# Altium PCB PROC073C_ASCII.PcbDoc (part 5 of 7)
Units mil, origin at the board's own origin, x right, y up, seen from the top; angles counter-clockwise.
Board outline 2165.35 x 2695.12 mil, 8 copper layers (Top Layer, L2_GND, L3_SIGNAL 1, L4_SIGNAL 2, L5_SIGNAL 3, L6_SIGNAL 4, L7_GND, Bottom Layer), stack 55.9 mil thick; 393 components, 319 nets, 1311 pads, 1643 vias.
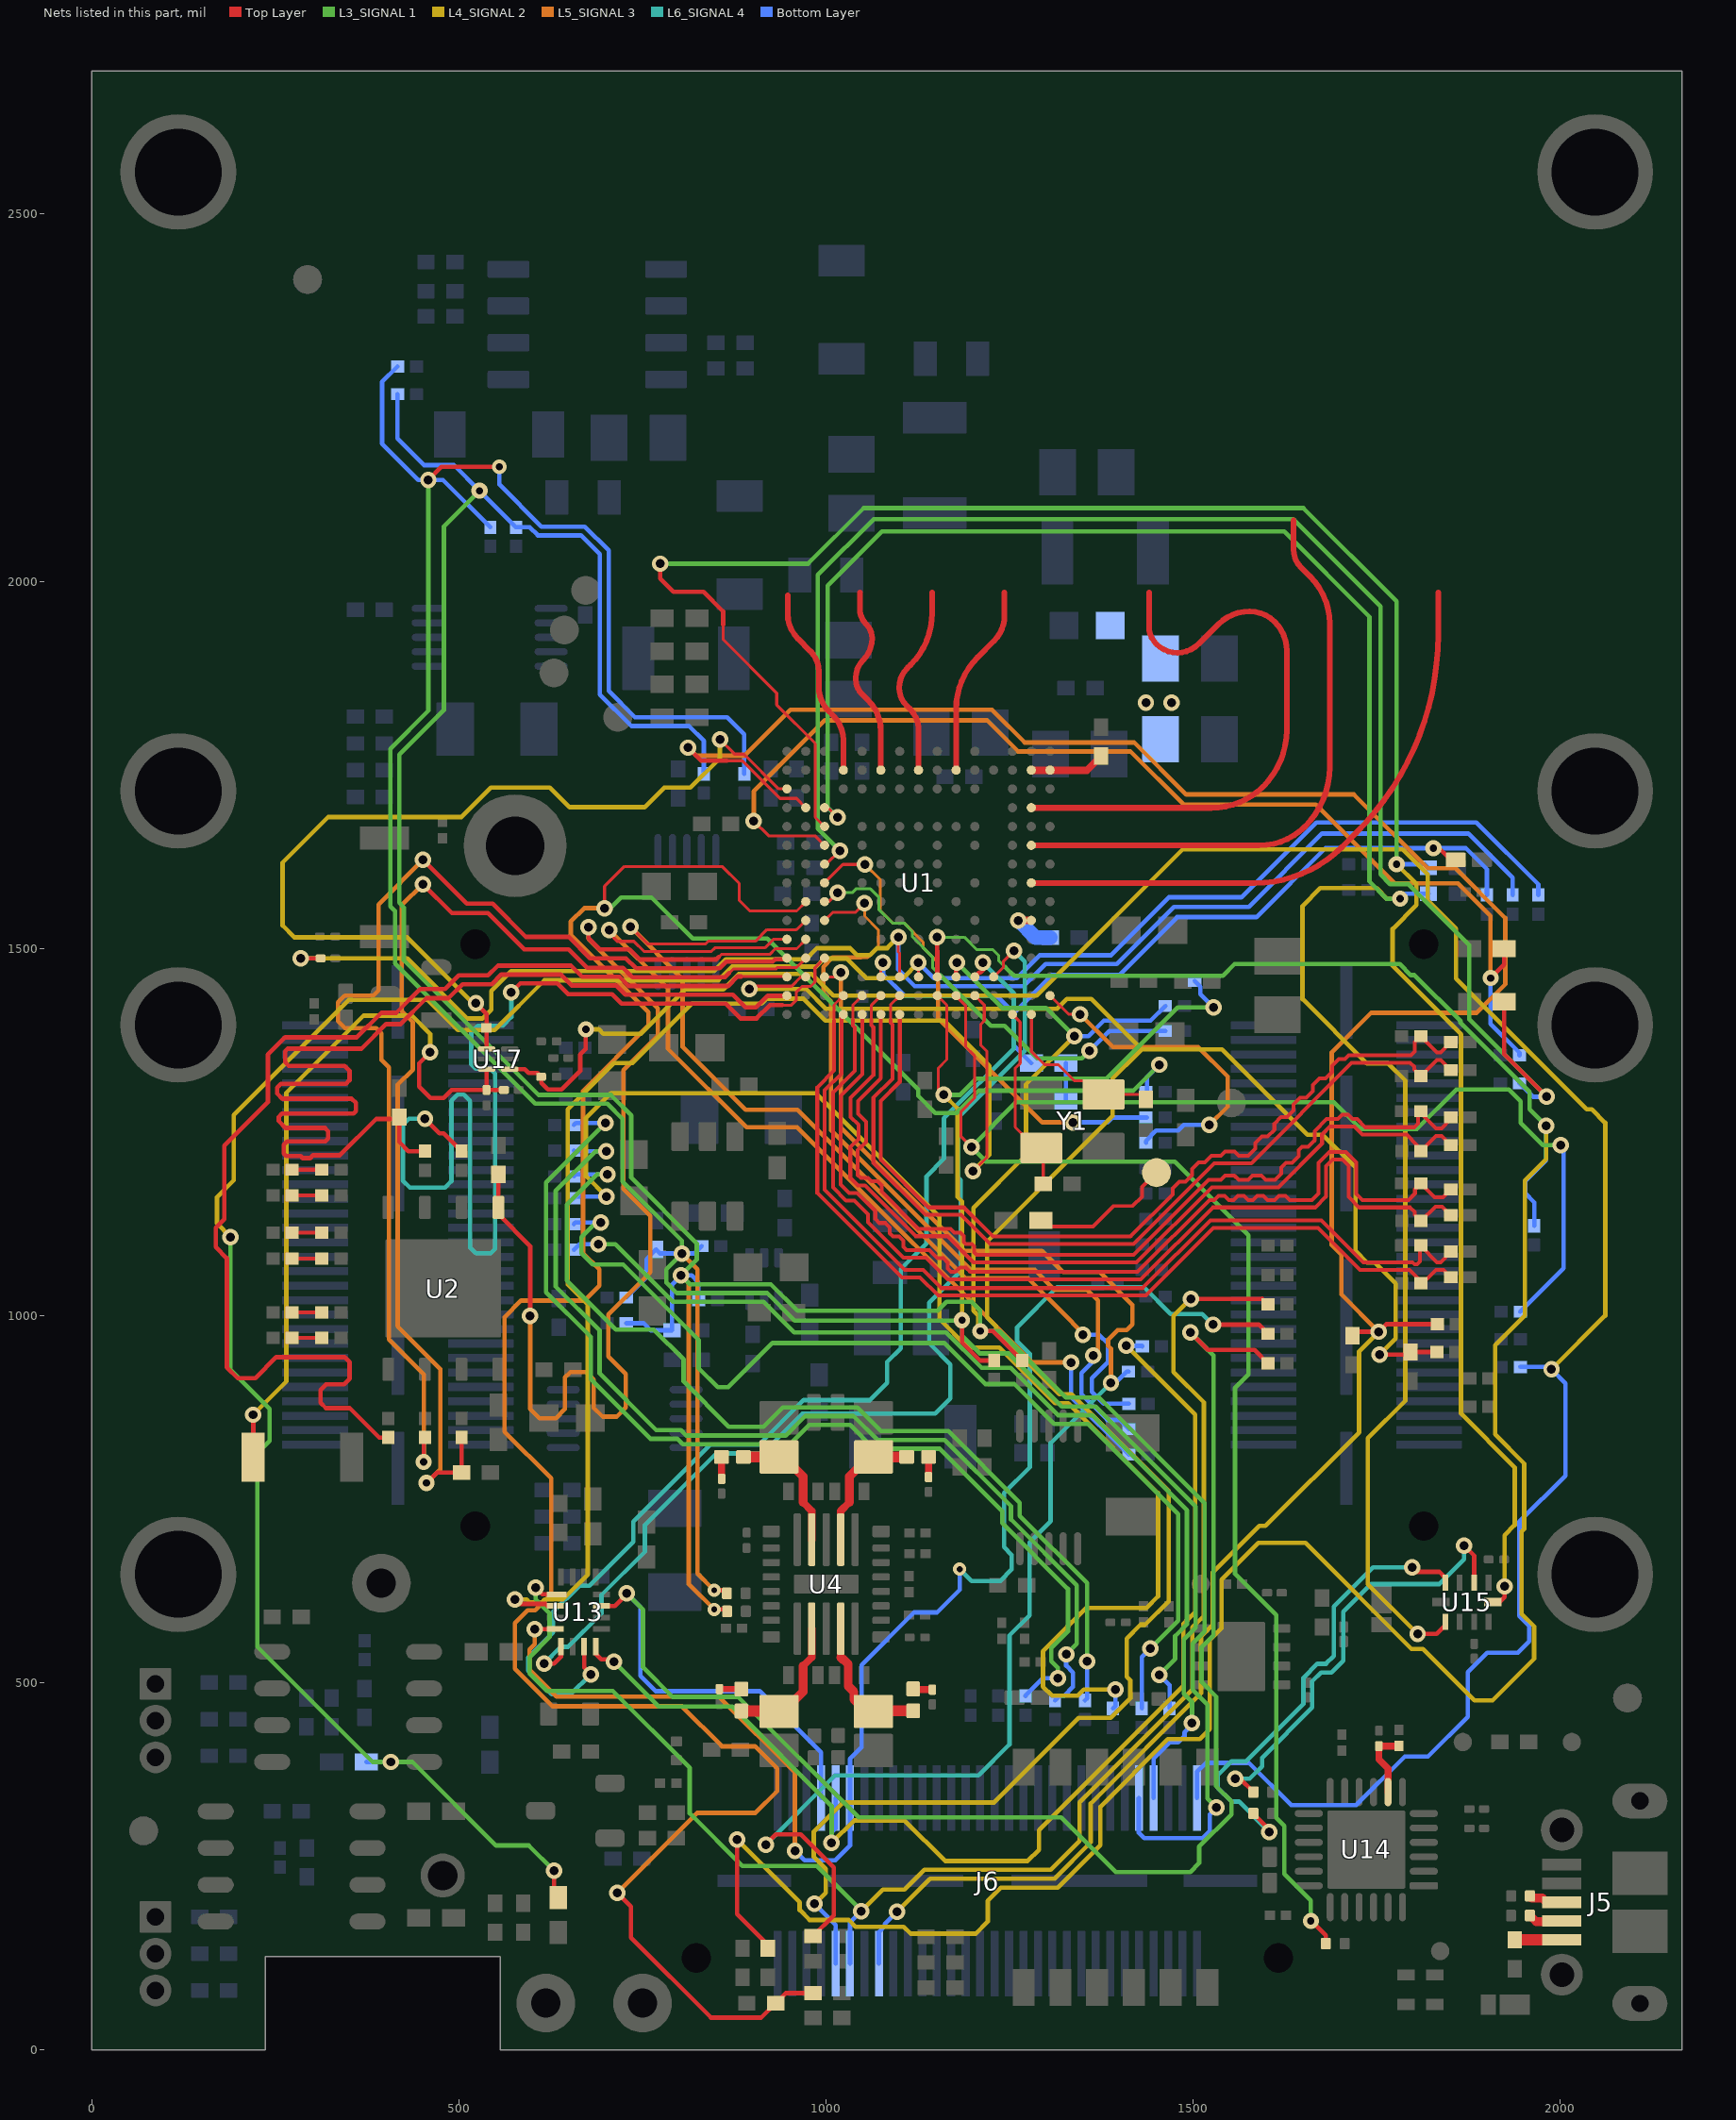
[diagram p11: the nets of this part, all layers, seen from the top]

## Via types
v1: diameter 15.74, hole 5.9, Top Layer to L2_GND, tented both sides, 894 vias
v2: diameter 22.4, hole 12.2, Top Layer to Bottom Layer, tented both sides, 510 vias
v3: diameter 18, hole 8, Top Layer to Bottom Layer, tented both sides, 74 vias
v4: diameter 15.75, hole 5.9, Top Layer to L2_GND, tented both sides, 72 vias
v5: diameter 22, hole 10, Top Layer to Bottom Layer, tented both sides, 61 vias
v6: diameter 19.68, hole 7.87, Top Layer to Bottom Layer, 16 vias
v7: diameter 15.74, hole 5.9, Top Layer to L2_GND, tented top, 14 vias
v8: diameter 20, hole 10, Top Layer to Bottom Layer, tented both sides, 1 vias
v9: diameter 15.75, hole 5.9, Top Layer to L2_GND, tented top, 1 vias

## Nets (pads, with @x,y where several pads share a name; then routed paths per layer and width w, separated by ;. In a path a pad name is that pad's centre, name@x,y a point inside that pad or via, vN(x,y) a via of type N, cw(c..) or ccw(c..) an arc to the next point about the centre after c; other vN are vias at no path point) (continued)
RADAR_DP10: R126.1 R163.1 | length 1440
  L3_SIGNAL 1 w6: v2(699.88,1262.31) 619.04,1181.47 619.04,1031.78 679.65,971.18 679.65,913.63 760.82,832.46 797.34,832.46 804.96,824.84 950.77,824.84 977.15,851.21 1032.87,851.21 1065.23,818.85 1155.14,818.85 1239.93,734.06 1239.93,717.61 1329.48,628.05 1329.48,569.87 1306.87,547.26 1306.87,529.59 1315.67,520.79 v2(1315.67,506.35)
  Bottom Layer w6: R126.1@656.74,1259.77 659.27,1262.31 v2(699.88,1262.31) ; R163.1@1271.67,482.2 1271.67,482.61 1295.41,506.35 v2(1315.67,506.35)
RADAR_DP11: R127.1 R164.1 | length 1390.6
  L3_SIGNAL 1 w6: v2(700.77,1224.08) 686.3,1224.08 631.92,1169.7 631.92,1039.89 691.77,980.04 691.77,921.47 768.79,844.46 802.31,844.46 809.93,836.84 944.98,836.84 971.35,863.21 1037.85,863.21 1070.2,830.85 1161.65,830.85 1251.93,740.57 1251.93,722.58 1341.48,633.03 1341.48,553.3 v2(1327.07,538.89)
  Bottom Layer w6: R127.1@656.74,1224.77 657.43,1224.08 v2(700.77,1224.08) ; R164.1@1311.95,476.21 1318.5,482.76 1324.58,482.76 1336.41,494.6 1336.41,514.17 1327.07,523.51 v2(1327.07,538.89)
RADAR_DP12: R128.1 R166.1 | length 1313
  L3_SIGNAL 1 w6: v2(702.64,1192.32) 687.92,1192.32 647.04,1151.44 647.04,1047.9 713.7,981.24 765.35,981.24 806.14,940.45 806.14,910.34 867.64,848.84 914.85,848.84 941.22,875.21 1042.82,875.21 1075.17,842.85 1166.62,842.85 1263.93,745.54 1263.93,727.55 1355.47,636 v2(1355.47,529.24)
  Bottom Layer w6: R128.1@656.74,1189.77 659.28,1192.32 v2(702.64,1192.32) ; R166.1@1352.68,476.21 1355.47,479 v2(1355.47,529.24)
RADAR_DP13: R129.1 R167.1 | length 1774.4
  L4_SIGNAL 2 w6: v2(701,1162.39) 673.21,1190.18 673.21,1269.31 706.86,1302.96 986.35,1302.96 1154.49,1134.82 1154.49,995.55 1193.3,956.74 1236.32,956.74 1312.09,880.97 1329.87,880.97 1452.29,758.55 1452.29,617.94 1436.42,602.07 1354.52,602.07 1295.47,543.01 1295.47,495.14 1307.84,482.76 1342.8,482.76 1351.01,490.97 v2(1394.13,490.97)
  Bottom Layer w6: R129.1@656.74,1159.77 659.35,1162.39 v2(701,1162.39) ; R167.1@1390.77,465.36 1394.13,468.72 v2(1394.13,490.97)
RADAR_DP14: R130.1 R168.1 | length 1411.3
  L3_SIGNAL 1 w6: v2(693.46,1126.8) 686.72,1126.8 666.87,1106.95 666.87,1085.41 682.46,1069.82 723.86,1069.82 826.64,967.04 826.64,928.67 852.61,902.69 867.01,902.69 927.16,962.84 1161.12,962.84 1216.94,907.02 1256.38,907.02 1310.83,852.56 1357.04,852.56 1479.54,730.07 1479.54,585.01 v2(1441.67,547.13)
  Bottom Layer w6: R130.1@656.74,1124.77 658.77,1126.8 v2(693.46,1126.8) ; R168.1@1429.92,465.36 1429.92,535.38 v2(1441.67,547.13)
RADAR_DP15: R132.1 R170.1 | length 1279.2
  L3_SIGNAL 1 w6: v2(690.39,1097.28) 713.37,1097.28 791.76,1018.88 915,1018.88 956.59,977.29 1163.64,977.29 1212.04,928.89 1251.48,928.89 1315.8,864.56 1362.01,864.56 1491.54,735.04 1491.54,580.04 1475.43,563.92 1475.43,532.9 v2(1453.69,511.16)
  Bottom Layer w6: R132.1@656.74,1089.77 664.24,1097.28 v2(690.39,1097.28) ; v2(1453.69,511.16) 1467.83,497.01 R170.1@1467.83,465.36
RADAR_GPIO_0: R3.2 R65.1 R216.2 U1.H13 | length 3456.1
  Top Layer w4: v2(1125.87,1480.63) 1125.97,1480.53 U1.H13@1125.98,1461.43
  Top Layer w6: v2(629.66,244.32) 629.66,213.6 R216.2@635.54,207.72
  L3_SIGNAL 1 w6: v2(189.22,1107.14) 189.22,926.5 242.35,873.38 242.35,829.52 225.74,812.92 225.74,549.14 382.47,392.41 v2(407.49,392.41) 436.79,392.41 550.58,278.62 595.36,278.62 v2(629.66,244.32)
  L4_SIGNAL 2 w6: v2(189.22,1107.14) 170.88,1125.48 170.88,1161.52 193.76,1184.4 193.76,1273.34 350.5,1430.09 457.6,1430.09 498.52,1389.16 549.01,1389.16 616.58,1456.73 853.54,1456.73 872.19,1475.39 986.79,1475.39 997.78,1486.39 1027.98,1486.39 1054.73,1459.63 1104.88,1459.63 v2(1125.87,1480.63)
  Bottom Layer w6: R3.2@374.13,392.41 v2(407.49,392.41) ; v2(1125.87,1480.63) 1146.7,1459.8 1260.03,1459.8 1290.94,1490.71 1387.94,1490.71 1467,1569.77 1565.72,1569.77 1667.66,1671.71 1885.71,1671.71 1970,1587.42 R65.1@1970,1572.76
RADAR_GPIO_1: R66.2 R214.2 U1.J13 | length 2022.3
  Top Layer w4: v2(1098.42,1515.43) 1098.42,1495.23 1100.38,1493.27 U1.J13@1100.39,1461.43
  Top Layer w6: v2(284.89,1486.65) R214.2@311.88,1486.65
  L4_SIGNAL 2 w6: v2(284.89,1486.65) 429.79,1486.65 511.81,1404.63 531.99,1404.63 544.12,1416.76 544.12,1442.11 571.24,1469.23 847.52,1469.23 863.68,1485.39 972.74,1485.39 987.85,1500.51 1032.72,1500.51 1042.13,1491.09 1060.05,1491.09 1069.46,1500.51 1083.5,1500.51 v2(1098.42,1515.43)
  Bottom Layer w6: v2(1098.42,1515.43) 1098.42,1471.34 1120.84,1448.93 1269.16,1448.93 1298.94,1478.71 1395.94,1478.71 1474,1556.77 1575.75,1556.77 1675.59,1656.61 1874.64,1656.61 1935,1596.25 R66.2@1935,1572.76
RADAR_GPIO_2: D7.1 R67.2 R185.2 U1.K13 | length 1149.4
  Top Layer w4: U1.K13@1074.8,1461.43 1074.79,1477.71 v2(1077.67,1480.59)
  Top Layer w6: v5(1827.1,1636.61) 1827.1,1637.93 1830.3,1641.13 1850.63,1620.81 D7.1@1857.59,1620.81
  Bottom Layer w6: v2(1077.67,1480.59) 1077.67,1465.1 1106.92,1435.86 1232.34,1435.86 1251.05,1417.15 ; R185.2@1279.5,1344.13 1256,1367.63 1256,1412.2 ; R67.2@1900,1572.76 1900,1608.03 1871.42,1636.61 v5(1827.1,1636.61) 1679.81,1636.61 1585.97,1542.77 1478,1542.77 1399,1463.77 1307.57,1463.77 1260.95,1417.15 ; 1251.05,1417.15 1256,1412.2 ; 1251.05,1417.15 1260.95,1417.15 ; 1256,1412.2 1260.95,1417.15
RADAR_HOSTINTR1: J6.10 R10.2 R152.2 U1.P13 | length 3227.2
  Top Layer w4: v2(895.59,1444.77) 899.55,1448.72 953.35,1448.72 965.85,1461.22 U1.P13@972.64,1461.22
  Top Layer w6: v2(1754.07,947.16) 1792.52,947.16 R152.2@1795.94,950.58 R10.2@1831.68,950.58
  L4_SIGNAL 2 w6: v2(895.59,1444.77) 973.05,1444.77 999.88,1417.94 1314.72,1417.94 1328.02,1431.24 1361.41,1431.24 1424.28,1368.37 ; v2(984.35,199.12) 999.65,214.42 999.65,246.71 983.46,262.9 983.46,297.43 1023.24,337.21 1228.81,337.21 1343.92,452.32 1387.89,452.32 1414.33,478.76 1414.33,503.62 1409.47,508.48 1409.47,560.46 1428.33,579.33 1434.57,579.33 1466.56,611.31 1466.56,761.25 1334.52,893.29 1317.77,893.29 1231.45,979.61 1231.45,985.86 1219.49,997.83 1219.49,1100.93 1390.36,1271.81 1390.36,1323.23 1424.28,1357.15 ; v2(1754.07,947.16) 1775.89,968.97 1775.89,1044.14 1747.57,1072.45 1736.75,1072.45 1721.01,1088.19 1721.01,1201.86 1676.32,1246.55 1655.67,1246.55 1539.46,1362.76 1429.89,1362.76 ; 1424.28,1357.15 1429.89,1362.76 ; 1424.28,1357.15 1424.28,1368.37 ; 1424.28,1368.37 1429.89,1362.76
  Bottom Layer w6: v2(984.35,199.12) 1013.05,170.43 J6.10@1013.05,117.69
RADAR_INTn: R184.1 R185.1 | length 51.8
  Bottom Layer w6: R184.1@1326.74,1292.36 R185.1@1326.74,1344.13
RADAR_LVDS_0M: R41.2 R230.2 U1.J15 | length 1201.9
  Top Layer w5.2: U1.J15@1100.59,1410.04 1100.59,1318.34 1074.79,1292.54 1074.79,1212.36 1139.67,1147.47 1187.93,1147.47 1227.63,1107.77 1414.67,1107.77 1472.09,1165.19 1472.09,1173.45 1481.04,1182.4 1489.29,1182.4 1498.36,1191.46 1498.36,1199.72 1507.31,1208.67 1515.57,1208.67 1524.63,1217.73 1537.76,1217.73 1543.6,1223.57 1556.26,1223.57 1562.1,1217.73 1574.91,1217.73 1584.35,1227.16 1584.35,1235.42 1593.3,1244.37 1601.56,1244.37 1610.62,1253.44 1610.62,1261.69 1619.57,1270.64 1627.83,1270.64 1636.89,1279.71 1636.89,1287.96 1645.84,1296.92 1654.1,1296.92 1663.16,1305.98 1663.16,1314.24 1672.11,1323.19 1680.37,1323.19 1689.43,1332.25 1689.43,1340.51 1698.38,1349.46 1706.64,1349.46 1711.65,1354.46 1796.37,1354.46 1801.8,1359.89 1801.8,1372.67 R230.2@1809.84,1380.71 1810.22,1380.32 1832.02,1358.52 1836.91,1358.52 R41.2@1850.8,1372.41
RADAR_LVDS_0P: R39.2 R229.2 U1.J14 | length 1203.4
  Top Layer w4: 1087.88,1402.84 1087.88,1423.35 U1.J14@1100.39,1435.84
  Top Layer w5.2: 1087.88,1402.84 1087.88,1398.83 1090.39,1396.32 1090.39,1322.57 1064.59,1296.77 1064.59,1208.13 1135.45,1137.28 1183.71,1137.28 1223.41,1097.57 1418.89,1097.57 1528.85,1207.53 1579.14,1207.53 1715.87,1344.26 1795.48,1344.26 1800.81,1338.93 1800.81,1335.25 R229.2@1809.84,1326.22 R229.2@1810.22,1326.6 ; R229.2@1810.26,1326.57 R229.2@1810.22,1326.6 ; R39.2@1850.8,1334.43 1836.91,1348.32 1831.94,1348.32 R229.2@1810.22,1326.6
RADAR_LVDS_1M: R35.2 R228.2 U1.K15 | length 1255.8
  Top Layer w5.2: U1.K15@1074.8,1410.25 1074.79,1323.47 1043.72,1292.4 1043.72,1274.8 1054.39,1264.13 1054.39,1236.34 1043.35,1225.3 1043.35,1191.73 1047.68,1187.41 1057.31,1187.41 1061.69,1183.02 1069.95,1183.02 1075.8,1177.17 1075.8,1168.92 1126.21,1118.5 1169.48,1118.5 1174.86,1113.12 1183.12,1113.12 1187.64,1108.6 1187.64,1100.34 1190.37,1097.61 1198.62,1097.61 1201.69,1094.55 1201.69,1086.29 1205.01,1082.97 1418.72,1082.97 1520.99,1185.24 1537.51,1185.24 1543.35,1191.08 1556.01,1191.08 1561.84,1185.24 1574.66,1185.24 1580.5,1191.08 1593.16,1191.08 1599,1185.24 1611.81,1185.24 1619.89,1193.33 1619.89,1201.58 1626.27,1207.96 1634.52,1207.96 1643.59,1217.02 1643.59,1225.28 1648.44,1230.13 1656.7,1230.13 1665.28,1238.71 1665.28,1251.05 1681.86,1267.63 1697.24,1267.63 1703.07,1273.47 1711.34,1273.47 1717.18,1267.63 1723.38,1267.63 1734.37,1256.65 1801.32,1256.65 1805.97,1261.31 1805.97,1274.65 R228.2@1809.84,1278.52 1809.84,1275.68 1830.33,1255.19 1838.34,1255.19 1850.8,1267.65 R35.2@1850.8,1270.22
RADAR_LVDS_1P: R33.2 R227.2 U1.K14 | length 1254.7
  Top Layer w4: 1061.87,1402.84 1061.87,1422.93 U1.K14@1074.8,1435.84
  Top Layer w5.2: 1061.87,1402.84 1061.87,1395.54 1064.59,1392.82 1064.59,1327.69 1033.52,1296.62 1033.52,1270.57 1044.19,1259.9 1044.19,1240.57 1033.52,1229.9 1033.15,1229.53 1033.15,1187.51 1043.45,1177.21 1053.08,1177.21 1121.98,1108.3 1165.25,1108.3 1200.79,1072.77 1422.94,1072.77 1525.22,1175.04 1616.04,1175.04 1675.48,1234.48 1675.48,1246.82 1686.09,1257.43 1719.16,1257.43 1730.14,1246.45 1790.86,1246.45 1805.16,1232.15 1805.16,1229.48 R227.2@1810.26,1224.38 1830.88,1244.99 1838.04,1244.99 R33.2@1850.8,1232.24
RADAR_LVDS_2M: R137.2 R224.2 | length 40.6
  Top Layer w5.2: R137.2@272.99,969.77 R224.2@313.6,969.77
RADAR_LVDS_2P: R136.2 R223.2 | length 40.6
  Top Layer w5.2: R136.2@272.99,1004.77 R223.2@313.6,1004.77
RADAR_LVDS_3M: R135.2 R222.2 | length 40.6
  Top Layer w5.2: R135.2@272.99,1078.02 R222.2@313.6,1078.02
RADAR_LVDS_3P: R134.2 R221.2 | length 40.6
  Top Layer w5.2: R134.2@272.99,1113.02 R221.2@313.6,1113.02
RADAR_LVDS_CLKM: R32.2 R226.2 U1.L15 | length 1338
  Top Layer w5.2: U1.L15@1049.41,1410.04 1049.41,1392.62 1049.4,1329 1019.78,1299.39 1019.78,1178.79 1031.58,1166.99 1042.55,1166.99 1067.21,1142.34 1067.21,1131.66 1072.61,1126.27 1080.86,1126.27 1086.71,1120.42 1086.71,1112.16 1091.1,1107.78 1099.35,1107.78 1105.2,1101.93 1105.2,1093.67 1109.59,1089.29 1140.54,1089.29 1151.67,1078.16 1159.93,1078.16 1165.77,1072.31 1165.77,1064.06 1170.16,1059.67 1176.36,1059.67 1182.2,1065.51 1190.47,1065.51 1196.31,1059.67 1424.27,1059.67 1522.26,1157.66 1528.8,1157.66 1534.64,1163.5 1542.91,1163.5 1548.75,1157.66 1554.95,1157.66 1560.79,1163.5 1569.06,1163.5 1574.89,1157.66 1581.1,1157.66 1586.94,1163.5 1595.61,1163.5 1601.45,1157.66 1610.84,1157.66 1616.68,1163.5 1625.64,1163.5 1631.48,1157.66 1661.78,1157.66 1670.6,1166.48 1670.6,1208.13 1685.54,1223.07 1707.71,1223.07 1722.02,1208.76 1722.02,1166.07 1730.42,1157.66 1793.15,1157.66 1802.02,1166.53 1802.02,1172.36 R226.2@1809.84,1180.18 1828.71,1161.32 1840.22,1161.32 R32.2@1850.8,1171.89
RADAR_LVDS_CLKP: R30.2 R225.2 U1.L14 | length 1346.1
  Top Layer w4: 1036.49,1402.62 1036.49,1422.71 U1.L14@1049.41,1435.63
  Top Layer w5.2: 1036.49,1402.62 1036.49,1395.32 1039.2,1392.61 1039.2,1333.23 1009.58,1303.61 1009.58,1174.56 1027.35,1156.79 1038.33,1156.79 1057.01,1138.11 1057.01,1127.44 1105.36,1079.09 1136.32,1079.09 1165.93,1049.47 1428.49,1049.47 1526.49,1147.46 1666,1147.46 1680.8,1162.26 1680.8,1203.91 1689.76,1212.87 1703.48,1212.87 1711.82,1204.54 1711.82,1161.84 1726.2,1147.46 1795.54,1147.46 1801.6,1141.41 1801.6,1137.69 R225.2@1810.26,1129.03 1829.86,1148.63 1839.06,1148.63 R30.2@1850.8,1136.89
RADAR_LVDS_FRCLKM: R24.2 R220.2 U1.M15 | length 1258.7
  Top Layer w5.2: U1.M15@1023.82,1410.04 1021.27,1407.5 1021.27,1329.73 998.4,1306.85 998.4,1171.32 1107.5,1062.22 1132.37,1062.22 1156.93,1037.66 1431.11,1037.66 1523.33,1129.89 1674.32,1129.89 1731.42,1072.79 1798.58,1072.79 1801.47,1069.89 1804.71,1069.89 1808.54,1073.73 1808.54,1093.74 R220.2@1809.84,1095.03 ; R220.2@1809.84,1095.72 R220.2@1809.84,1095.03 ; R24.2@1850.8,1087.42 1850.8,1086.58 1836.91,1072.7 1832.17,1072.7 R220.2@1809.84,1095.03
RADAR_LVDS_FRCLKP: R22.2 R219.2 U1.M14 | length 1285.9
  Top Layer w4: 1011.07,1401.47 1011.07,1423.3 U1.M14@1023.62,1435.84
  Top Layer w5.2: 1011.07,1401.47 1011.07,1333.95 988.2,1311.08 988.2,1167.1 1103.27,1052.02 1128.15,1052.02 1152.7,1027.47 1435.34,1027.47 1527.56,1119.69 1670.09,1119.69 1727.19,1062.59 1794.36,1062.59 1810.26,1046.68 R219.2@1810.26,1044.56 1812.79,1044.56 1830.59,1062.36 1840.86,1062.36 R22.2@1850.8,1052.42
RADAR_LVDS_VALIDM: R133.2 R218.2 | length 40.6
  Top Layer w5.2: R133.2@272.99,1163.84 R218.2@313.6,1163.84
RADAR_LVDS_VALIDP: R131.2 R217.2 | length 40.6
  Top Layer w5.2: R131.2@272.99,1198.84 R217.2@313.6,1198.84
RADAR_MCUCLKOUT: R62.2 U1.N8 | length 671
  Top Layer w4: U1.N8@998.03,1589.39 1007.57,1598.94 1007.57,1599 1023.06,1614.49 v2(1053.07,1614.49)
  L5_SIGNAL 3 w4: v2(1053.07,1614.49) 1073.87,1593.69 1073.87,1551.33 1090.58,1534.63 1106.38,1534.63 1132.27,1508.73 1132.27,1501.38 1152.74,1480.91 1152.74,1453.84
  L5_SIGNAL 3 w6: 1152.74,1453.84 1152.74,1405.22 1294.64,1263.32 v2(1336.33,1263.32)
  Bottom Layer w6: v2(1336.33,1263.32) 1383.35,1263.32 1389.8,1269.77 R62.2@1437.01,1269.77
RADAR_MISO1: U1.E14 U13.2 | length 1904.6
  Top Layer w4: v2(1200,1196.67) 1219.29,1215.96 1219.29,1359.77 1210.95,1368.11 1210.95,1397.1 1215.5,1401.65 1215.5,1423.09 U1.E14@1202.95,1435.63
  Top Layer w6: v2(576.47,613.51) 582.4,607.58 617.96,607.58 620.72,604.82 U13.2@631.29,604.82
  L4_SIGNAL 2 w6: v2(576.47,613.51) 592.29,613.51 596.31,609.49 613.05,609.49 617.07,613.51 641.66,613.51 675.76,647.61 675.76,1015.28 648.54,1042.5 648.54,1280.98 711.53,1343.97 736.64,1343.97 817.51,1424.84 912.52,1424.84 919.49,1431.82 969.06,1431.82 999.06,1401.81 1161.01,1401.81 1222.47,1340.35 1222.47,1219.14 v2(1200,1196.67)
RADAR_MOSI1: U1.D13 U13.5 | length 1511.4
  Top Layer w4: U1.D13@1228.54,1461.22 1241.43,1474.11 1241.43,1482.29 v2(1256.07,1496.94)
  Top Layer w6: v2(616.38,526.51) 629.95,526.51 639.17,535.72 U13.5@639.17,549.7
  L6_SIGNAL 4 w6: v2(616.38,526.51) 639.05,549.19 649.15,549.19 694.33,594.37 694.33,619.78 753.44,678.89 753.44,715 850.96,812.52 913.82,812.52 968,866.7 1148.95,866.7 1169.49,887.23 1169.49,933.77 1140.49,962.77 1140.49,1017.69 1183.66,1060.86 1183.66,1184.45 1179.75,1188.36 1179.75,1269.45 1270.88,1360.58 1270.88,1482.14 v2(1256.07,1496.94)
RADAR_MSS_LOGGER: R31.2 R96.2 U1.F14 | length 2847.5
  Top Layer w4: U1.F14@1177.16,1435.84 1177.15,1435.16 1189.87,1422.44 ; 1190.28,1422.03 1190.28,1366.12 1202.29,1354.12 1202.29,1296.09 1183.59,1277.39 1183.59,1244.26 v2(1197.95,1229.9)
  Top Layer w6: v5(1660.15,176.07) 1660.79,176.07 1680.69,156.17 R96.2@1680.69,145.26
  L3_SIGNAL 1 w6: v5(1660.15,176.07) 1660.15,203.84 1623.96,240.03 1623.96,305.54 1613.03,316.47 1613.03,592.63 1556.86,648.8 1556.86,901.54 1575.37,920.06 1575.37,1109.78 1475.19,1209.97 1376.46,1209.97 1217.88,1209.96 v2(1197.95,1229.9) 1258.78,1290.73 1691.76,1290.73 1728.06,1254.43 1804.48,1254.43 1858.29,1308.25 1929.75,1308.25 1946.07,1291.93 1946.07,1262.46 1976.13,1232.4 v2(2000.74,1232.4)
  Bottom Layer w6: R31.2@1945.35,1005.51 2004.53,1064.69 2004.53,1228.61 v2(2000.74,1232.4)
RADAR_NERR_OUT: R59.2 R169.1 U1.N6 | length 1558.3
  Top Layer w4: v2(901.68,1673.63) 921.88,1653.43 985.16,1653.43 U1.N6@998.23,1640.36
  Top Layer w6: v5(1905,1459.77) 1923.62,1478.39 R169.1@1923.62,1499.77
  L5_SIGNAL 3 w6: v2(901.68,1673.63) 901.68,1714.22 998.24,1810.79 1219.09,1810.79 1261.57,1768.31 1414.77,1768.31 1487.2,1695.88 1667.01,1695.88 1774.14,1588.74 1860.68,1588.74 1905,1544.42 v5(1905,1459.77)
  Bottom Layer w6: v5(1905,1459.77) 1905,1397.31 1944.29,1358.02 R59.2@1944.29,1354.7
RADAR_NERRIN: R58.2 R150.1 U1.N7 | length 2237.2
  Top Layer w4: U1.N7@998.03,1614.98 1000.46,1614.98 v2(1018.77,1633.29)
  Top Layer w6: R150.1@1923.62,1427.68 1923.62,1355.98 v2(1981.41,1298.19)
  L3_SIGNAL 1 w6: v2(1018.77,1633.29) 989,1663.06 989,2008.77 1065,2084.77 1636.12,2084.77 1755,1965.89 1755,1600.77 1768.01,1587.75 1793.19,1587.75 1876.06,1504.88 1876.06,1403.54 v2(1981.41,1298.19)
  Bottom Layer w6: R58.2@1944.29,1316.46 1962.57,1298.18 ; 1962.58,1298.19 v2(1981.41,1298.19)
RADAR_NRST: R171.1 U1.R3 U17.4 | length 1282.2
  Top Layer w4: v2(855.59,1784.77) 875.59,1764.77 888.22,1764.77 935.65,1717.34 U1.R3@946.84,1717.34
  Top Layer w6: v2(523.42,1425.33) 537.82,1410.93 R171.1@537.82,1391.99 U17.4@537.82,1363.26
  L4_SIGNAL 2 w6: v2(523.42,1425.33) 519.52,1425.33 429.54,1515.31 276.09,1515.31 260.09,1531.31 260.09,1616.75 322.38,1679.05 503.63,1679.05 543.89,1719.31 623.83,1719.31 650.75,1692.39 753.08,1692.39 779.77,1719.08 815.37,1719.08 855.59,1759.3 v2(855.59,1784.77)
RADAR_NRST_1: J6.59 R42.1 R123.2 U17.1 | length 3381.3
  Top Layer w6: U17.1@569.32,1335.7 590,1335.7 595.18,1330.51 607.03,1330.51 R123.2@612.21,1325.33 612.21,1317.3 621.65,1307.86 639.85,1307.86 665.35,1333.36 665.35,1355.41 672.99,1363.05 v5(672.99,1390.04)
  L4_SIGNAL 2 w6: v5(672.99,1390.04) 690.74,1390.04 696.81,1383.97 748.16,1383.97 808.58,1444.39 860.24,1444.39 881.25,1465.39 980.67,1465.39 1010,1436.07 1286.62,1436.07 1485.66,1635.11 1785.43,1635.11 1819.35,1601.19 1819.35,1565.8 1857.91,1527.23 1857.91,1459.16 2035.94,1281.13 2042.67,1281.13 2061.12,1262.68 2061.12,1000.11 v2(1987.95,926.94)
  Bottom Layer w6: J6.59@1505.17,343.28 1505.17,379.05 1517.27,391.15 1575.77,391.15 1633.49,333.43 1722,333.43 1788.22,399.66 1819.71,399.66 1873.75,453.7 1873.75,514.62 1900.4,541.27 1942.28,541.27 1957.43,556.42 1957.43,577.95 1944.25,591.13 1944.25,719.48 2006.94,782.17 2006.94,907.95 v2(1987.95,926.94) 1984.62,930.27 R42.1@1945.37,930.27
RADAR_NRST_2: C53.1 R165.1 S2.1 U17.6 | length 997
  Top Layer w6: S2.1@220.18,807.23 v2(220.18,865.17) ; v2(461.07,1358.57) 446.22,1343.72 446.22,1311.96 461.65,1296.52 479.22,1296.52 490.14,1307.45 R165.1@537.82,1307.45 ; U17.6@537.82,1335.7 R165.1@537.82,1307.45 ; C53.1@561.55,1307.45 R165.1@537.82,1307.45
  L4_SIGNAL 2 w6: v2(220.18,865.17) 265.25,910.24 265.25,1303.39 370.43,1408.57 436.38,1408.57 461.07,1383.88 v2(461.07,1358.57)
RADAR_OSC_CLKOUT: R61.2 U1.A14 | length 461.2
  Top Layer w4: U1.A14@1305.31,1435.63 1330.44,1410.51 v2(1346,1410.51)
  L5_SIGNAL 3 w6: v2(1346,1410.51) 1390.71,1365.8 1506.77,1365.8 1546.85,1325.72 1546.85,1284.62 v2(1522,1259.77)
  Bottom Layer w6: R61.2@1435.75,1235.48 1435.75,1238.19 1449.6,1252.04 1479.36,1252.04 1487.09,1259.77 v2(1522,1259.77)
RADAR_PMIC_CLKOUT_SOP2: R63.2 R202.1 R203.1 U1.P9 | length 3730.3
  Top Layer w4: v2(698.56,1554.97) 698.56,1584.73 725.59,1611.77 858.59,1611.77 881.8,1588.56 881.8,1565.56 896.27,1551.09 960.14,1551.09 U1.P9@972.64,1563.59
  Top Layer w6: v2(715.89,214.22) 734.49,195.63 734.49,153.16 843.39,44.26 911.78,44.26 R202.1@931.56,64.04 945.14,77.62 R203.1@982.36,77.62
  L3_SIGNAL 1 w6: v2(698.56,1554.97) 706.21,1554.97 720.86,1569.63 762.43,1569.63 818.57,1513.48 919.99,1513.48 1125.61,1307.86 1125.61,1299.4 1148.92,1276.1 1177.75,1276.1 1208.12,1306.47 1418.44,1306.47 v2(1453.74,1341.77)
  L5_SIGNAL 3 w6: v2(698.56,1554.97) 670.79,1554.97 652.46,1536.64 652.46,1518.95 758.13,1413.27 758.13,1395.21 669.26,1306.33 669.26,1085.4 691.56,1063.09 691.56,1040.69 671.52,1020.65 585.02,1020.65 562.4,998.03 562.4,841.92 625.82,778.5 625.82,620.93 603.99,599.11 593.96,599.11 576.37,581.51 576.37,519.5 627.72,468.14 803.67,468.14 858.16,413.65 903.5,413.65 933.62,383.52 933.62,352.61 904.09,323.07 824.74,323.07 v2(715.89,214.22)
  Bottom Layer w6: R63.2@1437.01,1304.77 1437.01,1325.04 v2(1453.74,1341.77)
RADAR_QSPI_CS: R50.2 U1.P11 U2.1 | length 1672.5
  Top Layer w4: 853.78,1488.34 857.41,1491.97 923.26,1491.97 931.06,1499.77 960.31,1499.77 U1.P11@972.33,1511.8
  Top Layer w6: R50.2@553.88,1192.5 U2.1@553.88,1147.43 553.88,1138.2 597.22,1094.86 v2(597.22,999.51) ; v2(676.77,1529.26) 676.77,1514.27 692.28,1498.77 732.63,1498.77 746.28,1485.11 850.55,1485.11 853.78,1488.34
  L5_SIGNAL 3 w6: v2(597.22,999.51) 597.22,873 609.74,860.49 632.21,860.49 644.66,872.94 644.66,916.03 652.08,923.44 673.53,923.44 683.91,913.06 683.91,874.59 695.93,862.57 715.16,862.57 727.58,875 727.58,920.73 703.68,944.63 703.68,1001.57 760.84,1058.74 760.84,1135.98 724.13,1172.69 724.13,1334.52 771.07,1381.45 771.07,1418.63 676.77,1512.93 v2(676.77,1529.26)
RADAR_QSPI_D0: R45.2 U1.R13 | length 1621.1
  Top Layer w4: 884.59,1461.97 946.3,1461.97 U1.R13@947.05,1461.22
  Top Layer w6: R45.2@403.88,834.2 391.76,834.2 351.77,874.19 319.21,874.19 311.83,881.56 311.83,899.03 319.22,906.41 343.68,906.41 351.38,914.11 351.38,936.53 344.31,943.6 251.56,943.6 223,915.03 199.07,915.03 184.2,929.9 184.2,1078.34 169.02,1093.52 169.02,1119.81 180.88,1131.67 180.88,1231.74 240.1,1290.96 240.1,1355.51 263.67,1379.08 361.18,1379.08 394.55,1412.45 414.9,1412.45 447.24,1444.78 481.53,1444.78 500.21,1463.46 540.01,1463.46 553.23,1476.68 653.08,1476.68 668,1461.77 718.71,1461.77 731.51,1448.97 866.71,1448.97 879.71,1461.97 884.59,1461.97
RADAR_QSPI_D1: R46.1 U1.N12 | length 1553.3
  Top Layer w4: 940.59,1422.84 952.87,1422.84 959.37,1429.34 959.37,1440.54 967.27,1448.44 979.17,1448.44 984.97,1454.24 984.97,1473.98 U1.N12@998.03,1487.02
  Top Layer w6: v2(454.04,1268.14) 473.8,1248.38 479.59,1248.38 R46.1@503.88,1224.09 ; v2(571.53,1440.25) 583.84,1452.56 633.98,1452.56 648.77,1437.77 708.77,1437.77 721.57,1424.97 863.54,1424.97 883.74,1404.77 905.59,1404.77 923.66,1422.84 940.59,1422.84
  L6_SIGNAL 4 w6: v2(454.04,1268.14) 432.26,1268.14 423.81,1259.7 423.81,1184.06 433.52,1174.35 481.14,1174.35 489.94,1183.15 489.94,1292.77 498.2,1301.03 506.96,1301.03 515.22,1292.77 515.22,1092.86 523.09,1084.99 543.6,1084.99 549.52,1090.91 549.52,1329.92 543.32,1336.12 523.2,1336.12 517.11,1342.21 517.11,1385.83 525.93,1394.65 559.55,1394.65 571.53,1406.63 v2(571.53,1440.25)
RADAR_QSPI_D2: R44.1 R47.1 U1.R14 | length 1637.7
  Top Layer w6: R47.1@453.88,1224.09 431.2,1224.09 418.88,1236.41 R44.1@418.88,1270.55 416.23,1267.89 387.54,1267.89 338.17,1218.52 301.64,1218.52 297.62,1214.5 287.46,1214.5 284.68,1217.28 264.91,1217.28 261.68,1220.51 261.68,1233.1 266.04,1237.46 318.45,1237.46 322.28,1241.3 322.28,1251.23 317.88,1255.63 264.34,1255.63 254.94,1265.03 254.94,1270.97 259.29,1275.32 356.56,1275.32 359.94,1278.7 359.94,1289.82 354.29,1295.48 259.65,1295.48 252.5,1302.63 252.5,1310.45 257.85,1315.79 346.31,1315.79 351.2,1320.68 351.2,1333.54 344.51,1340.22 268.42,1340.22 263.51,1345.14 263.51,1360.03 267.11,1363.63 367.8,1363.63 401.28,1397.11 420.8,1397.11 456.03,1432.34 486.06,1432.34 505.18,1451.46 544.98,1451.46 558.08,1464.56 638.95,1464.56 653.74,1449.77 713.74,1449.77 726.54,1436.97 873.39,1436.97 890.59,1419.77 904.72,1419.77 920.59,1435.63 U1.R14@947.05,1435.63
RADAR_QSPI_D3: R49.1 R51.2 U1.P12 | length 1559.9
  Top Layer w4: 868.06,1466.47 873.56,1471.97 931.63,1471.97 933.98,1474.32 960.14,1474.32 U1.P12@972.64,1486.82
  Top Layer w6: v2(451.09,1587.72) 490.72,1548.09 540.01,1548.09 589.07,1499.02 649.49,1499.02 674.74,1473.77 723.68,1473.77 736.48,1460.97 862.56,1460.97 868.06,1466.47 ; v5(456.08,772.35) 470.37,786.64 R49.1@503.88,786.64 R51.2@503.88,834.2
  L5_SIGNAL 3 w6: v2(451.09,1587.72) 422.45,1559.09 422.45,1414.61 437.48,1399.58 437.48,1334.98 416.76,1314.26 416.76,985.55 474.89,927.41 474.89,791.16 v5(456.08,772.35)
RADAR_QSPI_SCLK: R48.2 U1.R12 | length 1560.4
  Top Layer w4: U1.R12@945.56,1485.33 U1.R12@947.05,1486.82
  Top Layer w6: v2(451.35,1620.64) 511.03,1560.96 546.14,1560.96 591.22,1515.88 649.59,1515.88 678.71,1486.77 727.65,1486.77 741.31,1473.11 855.27,1473.11 864.13,1481.97 927.49,1481.97 930.85,1485.33 U1.R12@945.56,1485.33 ; v5(452.28,800.95) 452.28,832.59 R48.2@453.88,834.2
  L5_SIGNAL 3 w6: v2(451.35,1620.64) 390.66,1559.95 390.66,1442.75 383.72,1435.81 344.37,1435.81 335.38,1426.82 335.38,1401.37 345.24,1391.52 387.67,1391.52 394.64,1384.54 394.64,1348.29 404.76,1338.18 404.76,967.46 452.28,919.94 v5(452.28,800.95)
RADAR_RS232RX: R154.1 U1.N4 U15.6 | length 2925.6
  Top Layer w4: U1.N4@998.03,1691.75 1002.76,1691.75 v2(1015.87,1678.64)
  Top Layer w6: v2(1805.58,566.66) 1831.51,566.66 1843.23,578.36 U15.6@1843.23,583.41
  L3_SIGNAL 1 w6: v2(1015.87,1678.64) 1002.43,1692.08 1002.43,1994.2 1076,2067.77 1624,2067.77 1740,1951.77 1740,1591.24 1763.48,1567.75 v5(1781.63,1567.75)
  L4_SIGNAL 2 w6: v5(1781.63,1567.75) 1764.19,1567.75 1749.75,1582.19 1672.98,1582.19 1648.92,1558.13 1648.92,1431.11 1736.38,1343.64 1765.32,1343.64 1788.82,1320.14 1788.82,883.97 1737.97,833.12 1737.97,634.26 v2(1805.58,566.66)
  Bottom Layer w6: v5(1781.63,1567.75) 1788.64,1574.77 R154.1@1820.32,1574.77
RADAR_RS232TX: R153.1 U1.N5 U15.10 | length 3080.8
  Top Layer w4: 860,1940.72 860,1920.77 933,1847.77 933,1831.68 985.23,1779.45 985.23,1775.94 ; 985.28,1775.94 985.28,1678.9 U1.N5@998.23,1665.95
  Top Layer w6: v2(774.18,2023.95) 774.18,2003.84 792.25,1985.77 833.25,1985.77 860,1959.02 860,1940.72 ; U15.10@1908.19,609.98 1917.34,609.98 1924.05,616.69 v2(1924.05,631.38)
  L3_SIGNAL 1 w6: v2(774.18,2023.95) 975.6,2023.95 1051.42,2099.77 1650,2099.77 1777,1972.77 v5(1777,1614.77)
  L4_SIGNAL 2 w6: v5(1777,1614.77) 1803.82,1587.94 1803.82,1559.01 1771.55,1526.74 1771.55,1476.15 1864.71,1382.99 1864.71,866.59 1937.81,793.49 1937.81,714.95 1924.05,701.19 v2(1924.05,631.38)
  Bottom Layer w6: v5(1777,1614.77) 1815.31,1614.77 R153.1@1820.32,1609.77
RADAR_SCL: J6.53 R25.2 R37.1 R53.1 R56.1 R108.2 R109.2 R143.2 R159.2 R181.1 U1.G14 | length 5377.9
  Top Layer w4: U1.G14@1151.57,1435.84 1164.57,1422.84 1164.57,1348.78 1152.89,1337.1 1152.89,1308.47 v2(1160.59,1300.77)
  Top Layer w6: v2(458.56,2138.08) 476.39,2155.91 v8(555.26,2155.91) ; v3(847.84,626.16) 860.84,626.16 R181.1@865.01,622 ; v5(1185.29,993.99) 1185.29,963.43 1209.66,939.06 R25.2@1229.01,939.06
  L3_SIGNAL 1 w6: v2(458.56,2138.08) 458.56,1823.7 406.89,1772.03 406.89,1557.37 413.11,1551.14 413.11,1479.39 603.9,1288.61 702.15,1288.61 722.84,1267.92 722.84,1183.06 803.74,1102.16 v2(803.74,1084.77) 803.74,1084.34 782.54,1063.14 782.54,1045.07 796.73,1030.88 919.97,1030.88 957.36,993.49 v5@1185.29,993.49 ; v2(1160.59,1300.77) 1182.95,1300.77 1204.81,1322.63 1381.86,1322.63 1479,1419.77 v2(1528,1419.77) ; v5(1185.29,993.99) v5@1185.29,993.49 ; v2(1498.44,445.29) 1498.44,474.17 1487.43,485.19 1487.43,558.95 1503.54,575.07 1503.54,740.01 1366.98,876.57 1320.77,876.57 1248.59,948.75 1209.15,948.75 1185.29,972.61 v5@1185.29,993.49
  L5_SIGNAL 3 w6: v2(803.74,1084.77) 825.07,1063.44 825.07,648.93 v3(847.84,626.16)
  L4_SIGNAL 2 w6: v2(1160.59,1300.77) 1179.29,1282.07 1179.29,1161.51 1185.29,1155.51 v5(1185.29,993.99)
  Bottom Layer w6: R159.2@416.6,2292.44 395.56,2271.4 395.56,2187.37 444.85,2138.08 v2(458.56,2138.08) 478.48,2138.08 R108.2@542.98,2073.57 ; v8(555.26,2155.91) 555.26,2131.91 612.61,2074.56 671.51,2074.56 704.07,2041.99 704.07,1850.81 739.91,1814.97 865.27,1814.97 888.74,1791.5 R143.2@888.74,1737.76 ; R109.2@727.99,1024.77 755.45,1052.23 755.45,1076.8 R53.1@768.74,1090.09 774.06,1084.77 v2(803.74,1084.77) 820.75,1084.77 R56.1@830.75,1094.77 ; J6.53@1446.12,343.28 1446.12,397.12 1468,419.01 1479.55,419.01 1488.13,427.59 1488.13,432.45 1498.44,442.76 v2(1498.44,445.29) ; R37.1@1502.01,1455.77 1509.94,1447.84 1509.94,1437.83 v2(1528,1419.77)
RADAR_SDA: J6.51 R29.2 R34.1 R52.1 R55.1 R110.2 R111.2 R144.2 R160.2 R180.1 U1.F13 | length 5230.6
  Top Layer w6: v3(847.84,600.1) 847.94,600 862.85,600 R180.1@865.35,597.5 ; U1.F13@1177.16,1461.43 1177.15,1479.19 v2(1178.55,1480.59) ; v5(1209.96,979.06) 1227.18,979.06 R29.2@1267.18,939.06
  L3_SIGNAL 1 w6: v5(528.24,2123.32) 479.86,2074.94 479.86,1824.91 418.89,1763.94 418.89,1562.34 425.11,1556.11 425.11,1484.36 608.87,1300.61 707.12,1300.61 734.84,1272.89 734.84,1188.03 824.01,1098.86 824.01,1076.04 v2(802.74,1054.77) 814.63,1042.88 924.94,1042.88 961,1006.82 1151.75,1006.82 1164.11,1019.18 1198.12,1019.18 1209.96,1007.34 v5(1209.96,979.06) 1236,979.06 1326.49,888.57 1371.95,888.57 1515.54,744.98 1515.54,570.1 1499.43,553.98 1499.43,490.16 1519.25,470.34 1519.25,342.8 v2(1531.74,330.31) ; v2(1178.55,1480.59) 1240.23,1418.91 1299.85,1418.91 v2(1338,1380.77)
  L5_SIGNAL 3 w6: v2(802.74,1054.77) 813.07,1044.44 813.07,634.87 v3(847.84,600.1)
  L4_SIGNAL 2 w6: v5(1209.96,979.06) 1207.49,981.53 1207.49,1000.07 1200.61,1006.96 1200.61,1146.98 1272.38,1218.76 1272.38,1315.15 v2(1338,1380.77)
  Bottom Layer w6: R160.2@416.6,2254.9 416.6,2194.27 452.59,2158.28 493.28,2158.28 v5(528.24,2123.32) R110.2@577.98,2073.57 596.63,2073.57 607.64,2062.56 666.54,2062.56 692.07,2037.02 692.07,1845.84 734.94,1802.97 813.6,1802.97 833.74,1782.83 R144.2@833.74,1737.76 ; R111.2@727.99,989.77 751.86,989.77 761.52,980.11 R52.1@790.25,980.11 790.25,1042.27 v2(802.74,1054.77) 817.12,1054.77 826.49,1045.4 R55.1@826.49,1021.13 ; v2(1338,1380.77) 1357.42,1380.77 1378.42,1401.77 1442.01,1401.77 R34.1@1462.01,1421.77 ; J6.51@1426.43,343.28 1426.01,342.86 1426.01,295.92 1433.26,288.68 1513.09,288.68 1522.5,298.09 1522.5,321.06 v2(1531.74,330.31)
RADAR_SPICLK1: U1.E13 U13.7 | length 1531.8
  Top Layer w6: U13.7@670.66,549.7 670.66,520.93 v2(679.75,511.84) ; U1.E13@1202.75,1461.43 1208.65,1467.34 1210.37,1467.34 1213.87,1470.85 v2(1213.87,1480.84)
  L6_SIGNAL 4 w6: v2(679.75,511.84) 652.46,484.55 626.74,484.55 594.61,516.69 594.61,534.88 628.47,568.75 628.47,596.72 664.17,632.42 677.97,632.42 737.75,692.2 737.75,719.85 842.42,824.52 908.85,824.52 969.52,885.19 1059.99,885.19 1083.37,908.57 1083.37,937.09 1101.81,955.53 1101.81,1063.64 1136.93,1098.76 1136.93,1189.84 1160.59,1213.51 1160.59,1268.95 1255.75,1364.11 1255.75,1438.96 v2(1213.87,1480.84)
RADAR_SYNC_IN: J6.16 R36.2 R155.2 U1.P4 | length 3594.8
  Top Layer w4: 865.59,1755.77 885.9,1755.77 937.33,1704.34 959.84,1704.34 U1.P4@972.43,1691.75
  Top Layer w6: v2(812.12,1773.47) 829.82,1755.77 865.59,1755.77 ; R155.2@1717,972.62 1717.82,972.62 1723.38,978.18 v2(1752.62,978.18) 1762.83,988.39 R36.2@1832.36,988.39
  L5_SIGNAL 3 w6: v2(812.12,1773.47) 822.98,1762.61 889.45,1762.61 951.79,1824.95 1226.07,1824.95 1270.46,1780.56 1419.49,1780.56 1490.28,1709.77 1718.8,1709.77 1819.37,1609.2 1857.26,1609.2 1925,1541.46 1925,1451.49 1886.05,1412.53 1742.57,1412.53 1688.73,1358.7 1688.73,1096.11 1701.85,1082.99 1701.85,1028.95 v2(1752.62,978.18)
  L4_SIGNAL 2 w6: v2(1096.61,188.24) 1141.95,233.59 1311.05,233.59 1360.39,282.92 1360.39,335.8 1510.68,486.1 1510.68,563.23 1526.71,579.26 1526.71,650.54 1589.96,713.79 1598.57,713.79 1725.97,841.18 1725.97,951.53 v2(1752.62,978.18)
  Bottom Layer w6: J6.16@1072.1,117.69 1072.1,160.71 1080.28,168.89 1080.28,171.91 v2(1096.61,188.24)
RADAR_SYNC_OUT_SOP1: R16.2 R206.1 U1.G13 | length 3753.5
  Top Layer w6: v2(878.98,286.53) 878.98,185.24 920.56,143.66 R206.1@920.56,138.67 ; v2(1151.47,1515.39) 1151.47,1497.19 1151.56,1497.1 U1.G13@1151.57,1461.43
  L3_SIGNAL 1 w4: v2(1151.47,1515.39) 1188.38,1515.39 1205.21,1498.55 1227.21,1498.55 1235,1490.77 1235,1483.77 1244.04,1474.73
  L3_SIGNAL 1 w6: 1244.04,1474.73 1256,1462.77 1540.31,1462.77 1556.33,1478.79 1781.26,1478.79 1796.33,1463.72 1801.31,1463.72 1864.06,1400.97 1864.06,1398.57 1958.07,1304.56 1958.07,1281.28 v2(1980.54,1258.8)
  L4_SIGNAL 2 w6: v2(878.98,286.53) 964.15,201.36 964.15,190.76 977.66,177.25 1030.94,177.25 1040.15,168.04 1105.86,168.04 1115.28,158.63 1204.1,158.63 1220.31,174.83 1220.31,203.36 1238.01,221.06 1315.5,221.06 1373.53,279.09 1373.53,331.29 1465.65,423.4 1508.92,423.4 1522.68,437.16 1522.68,558.26 1538.71,574.29 1538.71,640.49 1588.91,690.69 1652.97,690.69 1797.21,546.45 1812.98,546.45 1883.03,476.4 1907.68,476.4 1964.19,532.91 1964.19,576.81 1947.1,593.91 1947.1,705.94 1950.75,709.59 1950.75,798.85 1911.27,838.33 1911.27,959.65 1951.84,1000.22 1951.84,1184.09 1980.54,1212.79 v2(1980.54,1258.8)
  Bottom Layer w6: R16.2@1964.4,1122.47 1964.4,1154.23 1952.1,1166.53 1952.1,1183.27 1980.54,1211.71 v2(1980.54,1258.8)
RADAR_TCK: R6.2 U1.P10 | length 1335.3
  Top Layer w4: v2(733.57,1529.75) 757.25,1506.11 835.53,1506.11 839.39,1509.97 903.92,1509.97 919.59,1525.64 959.83,1525.64 962.72,1528.53 962.82,1528.53 U1.P10@972.43,1538.2 U1.P10@972.43,1538.2
  L5_SIGNAL 3 w6: v2(733.57,1529.75) 804.72,1458.6 804.72,1366.24 890.58,1280.38 961.06,1280.38 1190.66,1050.78 1275.44,1050.78 1329.8,996.41 1341.63,984.57 1350.08,976.13 v2(1350.08,974.02)
  Bottom Layer w6: v2(1350.08,974.02) 1371.88,974.02 1384.26,961.64 1384.26,937.42 1361.84,915 1361.84,896.28 1377.95,880.18 R6.2@1412.44,880.18
RADAR_TDI: R5.1 U1.R11 | length 1341.9
  Top Layer w4: v2(705.17,1525.02) 705.17,1520.37 715.77,1509.77 738.37,1509.77 752.03,1496.11 843.97,1496.11 848.83,1500.97 916.79,1500.97 928.23,1512.41 U1.R11@947.05,1512.41
  L5_SIGNAL 3 w6: v2(705.17,1525.02) 784.88,1445.31 784.88,1363.49 891.73,1256.64 960.68,1256.64 1280.86,936.46 v2(1333.9,936.46)
  Bottom Layer w6: v2(1333.9,936.46) 1333.9,889.43 R5.1@1412.44,810.89
RADAR_TDO_SOP0: R4.2 R209.1 U1.N13 | length 2052.8
  Top Layer w4: U1.N13@998.03,1461.43 1014.37,1461.44 v2(1020.27,1467.34)
  Top Layer w6: v2(917.98,279.9) 931.91,293.83 965.6,293.83 1010.48,248.96 1010.48,183.53 R209.1@982.36,155.42 ; R209.1@982.36,154.42 R209.1@982.86,154.92
  L5_SIGNAL 3 w6: v2(1020.27,1467.34) 1020.27,1256.22 1188.33,1088.17 1293.91,1088.17 1322.79,1059.29 1372.95,1059.29 1417.45,1014.79 1417.45,988.44 1409.59,980.58 1397.09,980.58 1384.25,967.74 1384.25,958.82 1388,955.07 v2(1388,908.77)
  L6_SIGNAL 4 w6: v2(917.98,279.9) 1012.24,374.16 1207.85,374.16 1249.91,416.22 1249.91,564.62 1277.02,591.73 1277.02,691.56 1305.86,720.39 1305.86,826.63 v2(1388,908.77)
  Bottom Layer w6: v2(1388,908.77) 1394.19,908.77 1409.39,923.97 R4.2@1411.98,923.97
RADAR_TMS: R8.2 U1.N10 | length 1125.5
  Top Layer w4: U1.N10@998.03,1538.2 1008.97,1549.16 1039.8,1549.16 v2(1052.67,1562.03)
  L5_SIGNAL 3 w4.02: 1048,1487.77 1056.74,1487.77 1071.23,1502.26 1071.23,1525.54 1052.67,1544.09 v2(1052.67,1562.03)
  L5_SIGNAL 3 w6: 1048,1487.77 1009,1487.77 996.42,1475.19 996.42,1438.87 1006.92,1428.37 1006.92,1252.6 1196.75,1062.78 1283.99,1062.78 1311.47,1035.3 1355.69,1035.3 1370.28,1020.7 1370.28,952.01 v2(1364.06,945.79)
  Bottom Layer w6: v2(1364.06,945.79) 1364.06,938.05 1347.8,921.79 1347.8,893.35 1382.98,858.17 1399.8,858.17 R8.2@1412.44,845.53
RADAR_VBGAP: C6.2 U1.B10 | length 70.4
  Top Layer w10: v2(1262.07,1538.21) U1.B10@1279.52,1538.2
  Bottom Layer w20: v2(1262.07,1538.21) 1285.51,1514.77 C6.2@1305.31,1514.77
RADAR_VOUT_PA: C4.2 C7.2 C8.2 R1.2 U1.A2 U1.B2 | length 102.2
  Top Layer w10: U1.B2@1279.72,1742.72 1355.41,1742.72 C4.2@1374.18,1761.49
  other v2: 1435.59,1834.77 1470.59,1834.77
RADAR_VSENSE: R77.1 TP7.1 | length 199.3
  Top Layer w5: R77.1@1292.37,1129.77 1300.89,1121.25 1363.55,1121.25 1391.77,1149.47 1417.81,1149.47 1430.46,1162.12 1430.46,1175.23 TP7.1@1450,1194.77
RADAR_WARMRST: R64.2 U1.N9 | length 604.6
  Top Layer w4: U1.N9@998.03,1563.8 1003.79,1563.8 v2(1016.02,1576.03)
  L3_SIGNAL 1 w4: v2(1016.02,1576.03) 1035.72,1576.03 1040.92,1581.23 1060.63,1581.23 1071.87,1569.98 1071.87,1553.33 1090.58,1534.63 1106.38,1534.63 1117.62,1523.38 1117.62,1516.03 1145.07,1488.58 1145.07,1474.43 1155.24,1464.27
  L3_SIGNAL 1 w6: 1155.24,1464.27 1224.67,1394.84 1242.93,1394.84 1287.29,1350.47 1348.44,1350.47 v2(1358.74,1360.77)
  Bottom Layer w6: v2(1358.74,1360.77) 1385.74,1387.77 R64.2@1462.01,1387.77
RADAR_XTALM: C33.2 U1.C15 Y1.1 | length 257.6
  Top Layer w4: U1.C15@1253.93,1410.25 1264.41,1399.77 1264.41,1343.59 1257.72,1336.9 1257.72,1256.77 1286.14,1228.35 Y1.1@1293.27,1228.35 1295.9,1225.71 C33.2@1295.91,1179.77
RADAR_XTALP: C32.2 U1.B15 Y1.3 | length 233.3
  Top Layer w4: U1.B15@1279.72,1410.04 1279.72,1359.63 1297.59,1341.77 1316.59,1341.77 1338.59,1319.77 1359.33,1319.77 Y1.3@1377.91,1301.19 1428.86,1301.19 C32.2@1435.59,1294.46
RX1: U1.M2 | length 261.6
  Top Layer w7.79: 947.77,1980.95 947.77,1955.91 ccw(c995.92,1955.91) 961.87,1921.86 978.76,1904.97 cw(c951.21,1877.42) 990.17,1877.42 990.17,1856.99 ccw(c1039.3,1856.99) 1004.54,1822.27 1009.93,1816.88 cw(c976.89,1783.84) 1023.62,1783.84 U1.M2@1023.62,1742.93
RX2: U1.K2 | length 262.5
  Top Layer w7.79: 1046.2,1984.72 1046.2,1962.31 ccw(c1075.16,1962.31) 1054.68,1941.83 cw(c1035.22,1922.37) 1062.74,1922.37 cw(c1020.25,1922.37) 1050.29,1892.32 ccw(c1073.36,1869.26) 1040.74,1869.26 1040.74,1866.08 ccw(c1068.05,1866.08) 1048.73,1846.78 1057.06,1838.45 ; 1057.07,1838.44 cw(c1014.23,1795.63) 1074.8,1795.63 U1.K2@1074.8,1742.93
RX3: U1.H2 | length 262.2
  Top Layer w7.79: U1.H2@1125.98,1742.93 1125.98,1801.92 1125.74,1802.16 ccw(c1085.51,1797.77) 1114.13,1826.38 1109.64,1830.87 cw(c1133.54,1854.77) 1099.74,1854.77 cw(c1138.37,1854.77) 1111.05,1882.08 1115.34,1886.37 ccw(c1044.63,1957.08) 1144.63,1957.08 1144.63,1984.72
RX4: U1.F2 | length 262.7
  Top Layer w7.79: U1.F2@1177.16,1742.93 1177.16,1825.77 cw(c1277.16,1825.77) 1206.45,1896.48 1228.74,1918.77 ccw(c1194.2,1953.31) 1243.05,1953.31 1243.05,1984.72
SPI_CLK1: J6.9 R9.1 U13.8 | length 1690.7
  Top Layer w6: U13.8@686.41,549.7 686.41,539.74 694.11,532.04 708.13,532.04 v2(711.43,528.74)
  L3_SIGNAL 1 w6: v2(711.43,528.74) 772.46,467.71 872.58,467.71 1007.72,332.57 v2(1007.72,281.98)
  L4_SIGNAL 2 w6: v2(1007.72,281.98) 1038.41,312.67 1107.07,312.67 1162.16,257.59 1274.82,257.59 1289.97,272.73 1289.97,299.33 1486.68,496.04 1486.68,580.52 1502.56,596.41 1502.56,865.21 v2(1408.77,959.01)
  Bottom Layer w6: v2(1007.72,281.98) 1007.72,296.49 1013.05,301.81 J6.9@1013.05,343.28 ; v2(1408.77,959.01) 1430.08,959.01 R9.1@1430.75,958.34
SPI_CS1: J6.7 R7.1 U13.11 | length 2402
  Top Layer w6: U13.11@694.28,604.82 712.54,604.82 v2@729.6,621.88 ; v2(1496.11,977.44) 1520.07,953.48 1583.48,953.48 R7.1@1601.77,935.2
  L3_SIGNAL 1 w6: v2(728.65,621.88) 750.89,599.64 750.89,521.14 791,481.03 880.51,481.03 1044.61,316.93 1320.19,316.93 1394.5,242.62 1496.27,242.62 1508.1,254.45 1508.1,276.83 1551.94,320.67 1551.94,338.67 1531.25,359.37 1531.25,481.37 1511.43,501.19 1511.43,549.01 1527.54,565.12 1527.54,946.01 v2(1496.11,977.44)
  Bottom Layer w6: v2(728.65,621.88) 747.36,603.17 747.36,509.51 768.07,488.8 910,488.8 993.36,405.44 J6.7@993.36,343.28
SPI_MISO1: J6.12 R12.2 U13.1 | length 2149.7
  Top Layer w6: v2(604.68,629.69) 613.8,620.57 U13.1@633.26,620.57 ; v2(1496.92,1022.73) 1593.69,1022.73 1594.05,1023.08 R12.2@1601.77,1015.36
  L3_SIGNAL 1 w6: v2(604.68,629.69) 604.68,613.89 623.62,594.95 623.62,562.32 596.18,534.88 596.18,512.94 620.15,488.97 709.7,488.97 814.53,384.15 814.53,322.41 886.21,250.73 987.77,250.73 1048.02,190.48 v2(1048.02,189.02)
  L4_SIGNAL 2 w6: v2(1048.02,189.02) 1077.71,218.71 1107.19,218.71 1134.06,245.59 1306.08,245.59 1345.13,284.63 1345.13,337.52 1498.68,491.07 1498.68,575.55 1514.56,591.44 1514.56,881.94 1473.02,923.49 1473.02,999.53 1496.22,1022.73 v2(1496.92,1022.73)
  Bottom Layer w6: J6.12@1032.73,117.69 1032.73,173.73 v2(1048.02,189.02)
SPI_MOSI1: J6.11 R11.1 U13.4 | length 1987.7
  Top Layer w6: v2(603.42,573.33) U13.4@631.29,573.33 ; v2(1527.06,987.89) 1589.16,987.89 R11.1@1601.77,975.28
  L5_SIGNAL 3 w6: v2(603.42,573.33) 603.42,552.73 596.18,545.49 596.18,518.14 632.8,481.51 853.93,481.51 957.67,377.77 v2(957.67,271.42)
  L6_SIGNAL 4 w6: v3(1182.1,654.92) 1198.23,638.79 1237.26,638.79 1253.02,654.56 1253.02,674.31 1242.53,684.8 1242.53,758.77 1277.64,793.88 1277.64,947.98 1260.29,965.34 1260.29,984.31 1314.56,1038.58 1433.33,1038.58 1469.42,1002.49 1512.46,1002.49 v2(1527.06,987.89)
  Bottom Layer w6: v2(957.67,271.42) 970.79,258.3 1012.83,258.3 1032.73,278.2 J6.11@1032.73,343.28 1032.73,396.74 1048.56,412.57 1048.56,524.49 1120.1,596.03 1151.21,596.03 1182.07,626.88 v3(1182.1,654.92)
SW0: L4.2 R173.2 U4.10 | length 179.3
  Top Layer w10: 968.83,523.01 980.64,534.82 U4.10@980.64,573.85
  Top Layer w12: L4.2@941.96,461.17 968.83,488.04 968.83,523.01
  Top Layer w15: R173.2@884.8,461.74 L4.2@935.38,461.74
SW0_CAP: C54.1 R173.1 | length 30
  Top Layer w8: C54.1@854.8,491.55 R173.1@884.8,491.55
SW1: L5.2 R175.2 U4.12 | length 191
  Top Layer w10: 1020.01,534.82 U4.12@1020.01,573.85
  Top Layer w12: 1020.01,534.82 1022.61,532.23 1023.88,532.23 1030.33,525.78 1030.33,495.67 1038,488 1038,477.9 1054.73,461.17 L5.2@1058.7,461.17
  Top Layer w15: L5.2@1059.55,462.03 R175.2@1118.8,462.03
SW1_CAP: C55.1 R175.1 | length 26.4
  Top Layer w10: R175.1@1118.8,491.83 1119.74,490.9 C55.1@1144.8,490.9
SW2: L6.2 R178.2 U4.25 | length 183
  Top Layer w10: 968.83,745.95 980.64,734.14 U4.25@980.64,695.11
  Top Layer w12: L6.2@941.96,807.79 968.83,780.92 968.83,745.95
  Top Layer w15: R178.2@887.71,807.65 941.82,807.65 L6.2@941.96,807.79
SW2_CAP: C56.1 R178.1 | length 29.7
  Top Layer w10: C56.1@857.9,777.91 R178.1@857.9,807.65
SW3: L8.2 R183.2 U4.23 | length 173.9
  Top Layer w10: U4.23@1020.01,695.11 1020.01,734.14 1031.83,745.95
  Top Layer w12: 1031.83,745.95 1031.83,780.92 L8.2@1058.7,807.79
  Top Layer w15: L8.2@1058.7,807.79 L8.2@1064.7,807.79 R183.2@1103.9,807.79
SW3_CAP: C60.1 R183.1 | length 27.5
  Top Layer w10: C60.1@1139.71,780.26 R183.1@1139.71,807.79
TX1: U1.B4 | length 820.5
  Top Layer w7.79: U1.B4@1279.72,1691.54 1524.9,1691.54 ccw(c1524.9,1791.54) 1595.61,1720.83 ccw(c1518.88,1797.56) 1627.4,1797.56 1627.39,1905.36 ccw(c1571.48,1905.36) 1611.02,1944.9 ccw(c1576.8,1910.68) 1576.8,1959.07 ccw(c1576.8,1898.72) 1534.13,1941.39 1507.64,1914.9 cw(c1478.35,1944.19) 1478.35,1902.77 cw(c1478.35,1943.09) 1449.84,1914.58 cw(c1473.81,1938.55) 1439.91,1938.55 1439.91,1984.74
TX2: U1.B6 | length 820.5
  Top Layer w7.79: U1.B6@1279.72,1640.36 1589.93,1640.36 ccw(c1589.93,1728.74) 1652.42,1666.24 ; 1636.76,2083.17 1636.76,2043.26 ccw(c1671.2,2043.26) 1646.84,2018.91 1659.37,2006.38 cw(c1595.52,1942.53) 1685.82,1942.53 1685.82,1746.87 cw(c1571.8,1746.87) 1652.42,1666.24 ; 1652.47,1666.28 cw(c1575.03,1743.64) 1652.42,1666.24
TX3: U1.B8 | length 820.6
  Top Layer w7.79: U1.B8@1279.52,1589.39 1279.72,1589.18 1566.14,1589.18 1583.77,1589.18 ccw(c1583.77,1757.69) 1702.92,1638.54 1721.82,1657.43 ccw(c1451.93,1927.31) 1833.61,1927.31 1833.61,1984.74
USB_5V: J5.1 L9.1 | length 64.1
  Top Layer w15.75: L9.1@1937.91,150.2 J5.1@2001.97,150.2
USB_AR_RS232RX: R98.1 U15.4 | length 646.2
  Top Layer w6: R98.1@1582.03,322.25 1603.77,300.52 v2(1603.76,297.18) ; v2(1798.22,657.33) 1804.26,651.29 1835.16,651.29 1843.23,643.22 U15.4@1843.23,636.55
  L6_SIGNAL 4 w6: v2(1603.76,297.18) 1562.45,338.49 1552.12,338.49 1533.61,357 1533.61,374.39 1552.34,393.12 1571.83,393.12 1650.16,471.46 1650.16,507.25 1669.02,526.11 1680.84,526.11 1691.54,536.81 1691.54,604.19 1744.68,657.33 v2(1798.22,657.33)
USB_AR_RS232TX: R97.2 U15.2 | length 608.9
  Top Layer w6: v2(1557.38,369.6) 1563.8,369.6 R97.2@1582.03,351.37 ; v2(1868.84,686.91) 1882.6,673.15 U15.2@1882.6,636.55
  L6_SIGNAL 4 w6: v2(1557.38,369.6) 1576.87,369.6 1593.82,386.55 1593.82,398.15 1662.16,466.49 1662.16,502.28 1673.99,514.11 1688.51,514.11 1704.44,530.04 1704.44,596.91 1742.19,634.67 1835.15,634.67 1868.84,668.36 v2(1868.84,686.91)
USB_DM: J5.2 R92.2 | length 47.4
  Top Layer w12: R92.2@1958.5,183.31 1966.98,174.83 2001.01,174.83 J5.2@2001.97,175.79
USB_DP: J5.3 R91.2 | length 47
  Top Layer w12: R91.2@1958.5,209.97 1961.37,207.1 1975.59,207.1 1981.3,201.38 J5.3@2001.97,201.38
VBUS: R90.2 R95.2 U14.8 | length 95.1
  Top Layer w9.42: U14.8@1765.34,351.37 1765.34,383.46 1752.9,395.9 R95.2@1752.9,413.96 R90.2@1780.23,413.96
